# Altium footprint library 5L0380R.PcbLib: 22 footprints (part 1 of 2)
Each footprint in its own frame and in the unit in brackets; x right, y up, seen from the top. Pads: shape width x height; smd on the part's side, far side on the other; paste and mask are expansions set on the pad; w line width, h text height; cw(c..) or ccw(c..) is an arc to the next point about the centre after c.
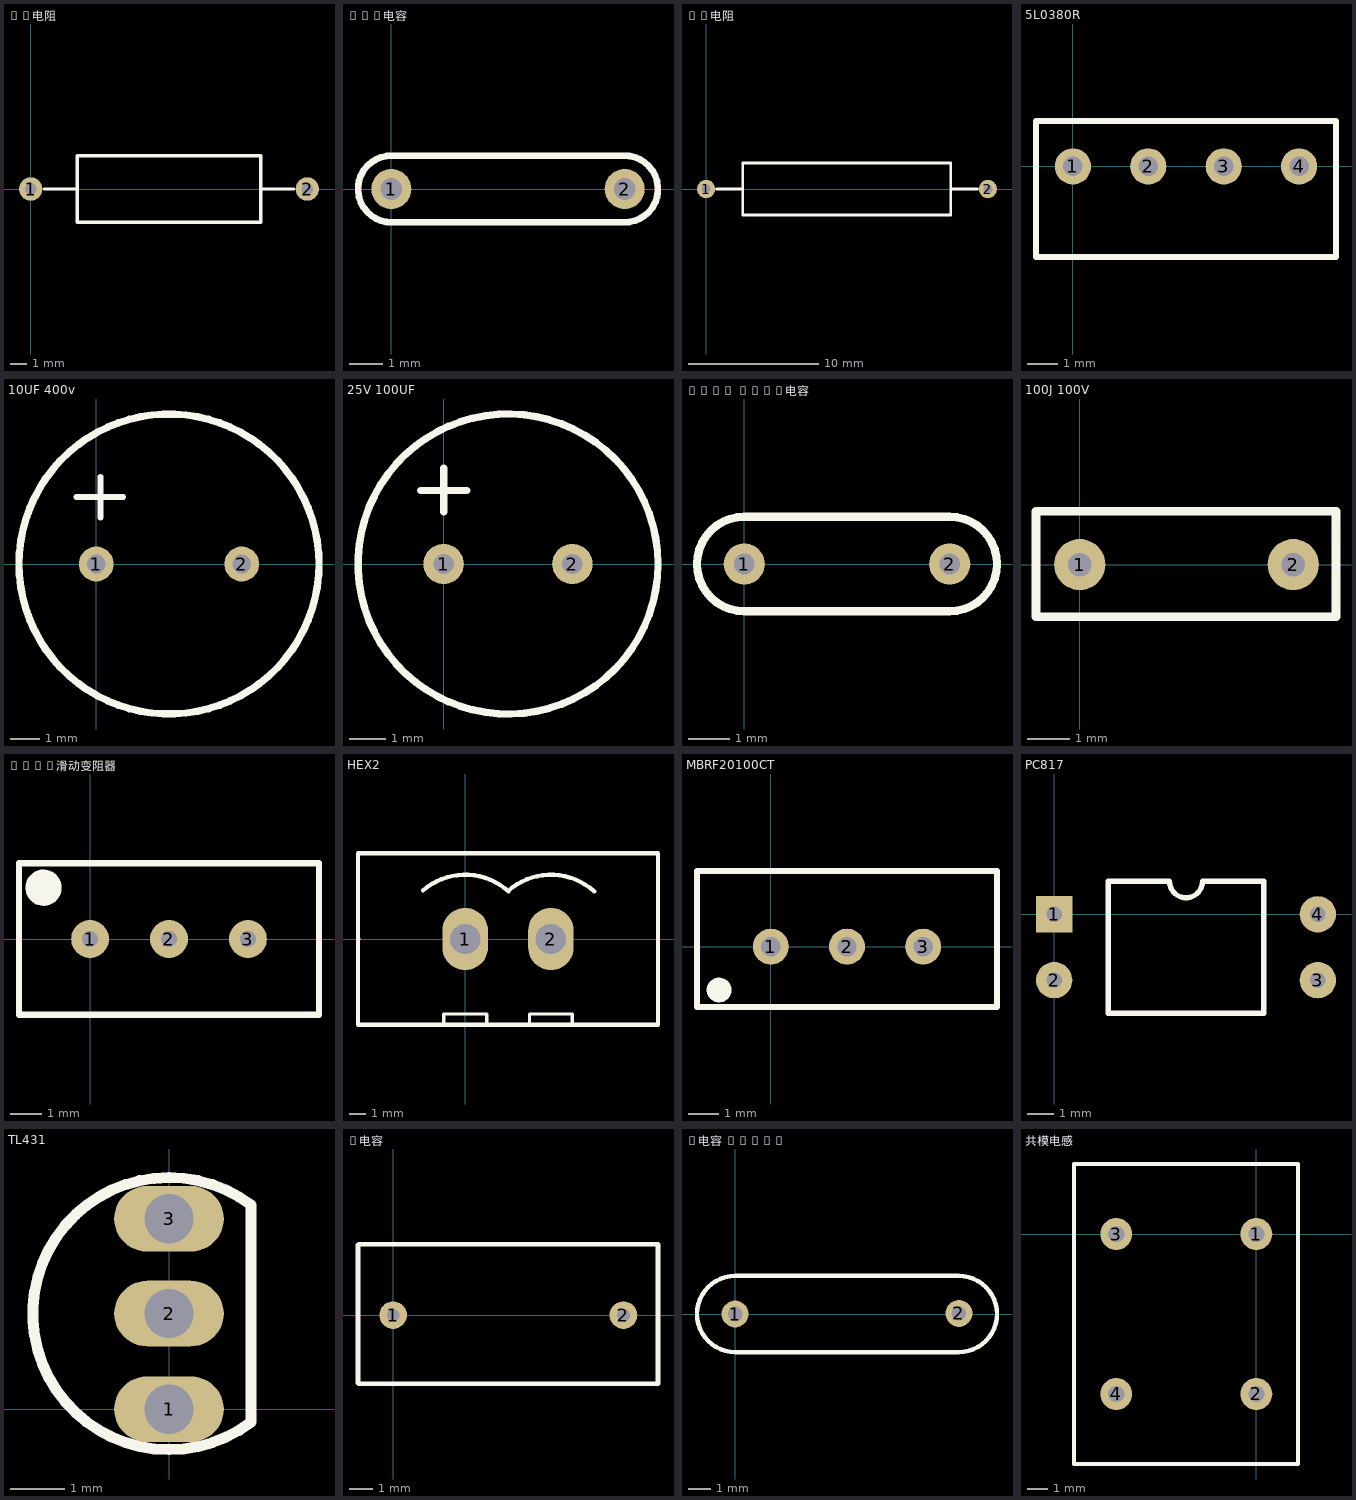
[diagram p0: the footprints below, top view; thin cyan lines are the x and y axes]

## 1W电阻 [mm]
pads (2):
  round 1.4 hole 0.7: 1(0,0) 2(16.6,0)
Top Overlay:
  lines w0.2: 0.8,0 2.8,0 ; 13.8,0 15.8,0 ; 2.8,-2 13.8,-2 13.8,2 2.8,2 2.8,-2

## 2KV电容 [mm]
pads (2):
  round 1.2 hole 0.65: 1(0,0) 2(7,0)
Top Overlay:
  lines w0.2: 6.974,1 cw(c7,0) 6.977,-1 ; 6.974,1 6.974,1 ; 6.974,1 0.023,1 ccw(c0,0) 0.026,-1 6.977,-1 ; 6.977,-1 6.977,-1

## 2W电阻 [mm]
pads (2):
  round 1.4 hole 0.7: 1(0,0) 2(21.641,0)
Top Overlay:
  lines w0.2: 0.8,0 2.8,0 ; 18.847,0 20.847,0 ; 2.8,-2 2.8,2 18.802,2 18.802,-2 2.8,-2

## 5L0380R [mm]
pads (4):
  round 1.2 hole 0.65: 1(0,0) 2(2.5,0) 3(5,0) 4(7.5,0)
Top Overlay:
  lines w0.2: -1.225,-3 8.725,-3 8.725,0 8.725,1.5 7.5,1.5 0,1.5 -1.225,1.5 -1.225,-3

## 10UF 400v [mm]
pads (2):
  round 1.2 hole 0.65: 1(0,0) 2(5,0)
Top Overlay:
  circle w0.254: c2.5,0 r5.157
  lines w0.2: -0.675,2.3 0.925,2.3 ; 0.15,1.6 0.15,3

## 25V 100UF [mm]
pads (2):
  round 1.1 hole 0.55: 1(0,0) 2(3.5,0)
Top Overlay:
  circle w0.2: c1.75,0 r4.079
  lines w0.2: -0.625,2 0.625,2 ; 0,1.425 0,2.6

## 33NF 100V电容 [mm]
pads (2):
  round 1 hole 0.5: 1(0,0) 2(5,0)
Top Overlay:
  lines w0.2: 0,-1.15 cw(c0,0) 0,1.15 5,1.15 cw(c5,0) 5,-1.15 0,-1.15

## 100J 100V [mm]
pads (2):
  round 1.2 hole 0.55: 1(0,0) 2(5,0)
Top Overlay:
  lines w0.2: -1.025,-1.225 6,-1.225 6,1.25 0,1.25 -1.025,1.25 -1.025,-1.225

## 100R滑动变阻器 [mm]
pads (3):
  round 1.2 hole 0.5: 1(0,0) 2(2.5,0) 3(5,0)
Top Overlay:
  circle w0.254: c-1.475,1.625 r0.025
  circle w0.254: c-1.475,1.6 r0.224
  circle w0.254: c-1.475,1.625 r0.447
  lines w0.2: -2.25,-2.4 -2.25,2.4 7.25,2.4 7.25,-2.4 -2.25,-2.4

## HEX2 [mm]
pads (2):
  oval 2.7x3.7 hole 1.8: 1(0,0) 2(5.08,0)
Top Overlay:
  lines w0.2: -1.27,-5.08 -1.27,-4.445 1.27,-4.445 1.27,-5.08 ; 3.81,-5.08 3.81,-4.445 6.35,-4.445 6.35,-5.08
  lines w0.254: -6.35,-0.025 -6.325,0 ; -2.5,2.875 cw(c0,0) 2.563,2.819 ; 2.542,2.842 cw(c5.08,0) 7.643,2.819 ; -6.35,-5.08 11.425,-5.08 11.425,5.08 -6.35,5.08 -6.35,-5.08

## MBRF20100CT [mm]
pads (3):
  round 1.2 hole 0.65: 1(0,0) 2(2.54,0) 3(5.08,0)
Top Overlay:
  circle w0.2: c-1.598,-1.448 r0.173
  circle w0.2: c-1.727,-1.448 r0.13
  circle w0.2: c-1.727,-1.448 r0.314
  lines w0.2: 7.544,2.489 7.544,-2.007 -2.464,-2.007 -2.464,2.515 7.544,2.515

## PC817 [mm]
pads (4):
  rect 1.4x1.4 hole 0.6: 1(0,0)
  round 1.4 hole 0.6: 2(0,-2.54) 3(10.16,-2.54) 4(10.16,0)
Top Overlay:
  lines w0.2: 2.085,-3.81 2.085,1.27 4.445,1.27 ccw(c5.08,1.27) 5.715,1.27 8.075,1.27 8.075,-3.81 2.085,-3.81

## TL431 [mm]
pads (3):
  oval 2x1.2 hole 0.9: 1(0,0) 2(0,1.745) 3(0,3.475)
Top Overlay:
  lines w0.2: 1.5,-0.235 cw(c0,1.745) 1.5,3.725 1.5,-0.235
Mechanical 13:
  lines w0.1: 1.5,-0.235 cw(c0,1.745) 1.5,3.725 1.5,-0.235
Mechanical 15:
  lines w0.1: -0.5,1.745 0.5,1.745 ; 0,1.245 0,2.245

## X电容 [mm]
pads (2):
  round 1.2 hole 0.55: 1(0,0) 2(10,0)
Top Overlay:
  lines w0.2: -1.525,-2.95 -1.525,3.05 ; -1.5,-2.975 11.5,-2.975 ; -1.5,3.075 11.5,3.075 11.5,-2.925

## Y电容 2.2NF [mm]
pads (2):
  round 1.2 hole 0.65: 1(0,0) 2(10,0.025)
Top Overlay:
  lines w0.2: 0,-1.7 cw(c0,0) 0,1.7 10,1.7 cw(c10,0) 10,-1.7 0,-1.7

## 共模电感 [mm]
pads (4):
  round 1.6 hole 0.8: 1(0,0) 2(0,-8) 3(-7,0) 4(-7,-8)
Top Overlay:
  lines w0.2: -9.1,-11.5 2.075,-11.5 2.075,3.5 -9.1,3.5 -9.1,-11.5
